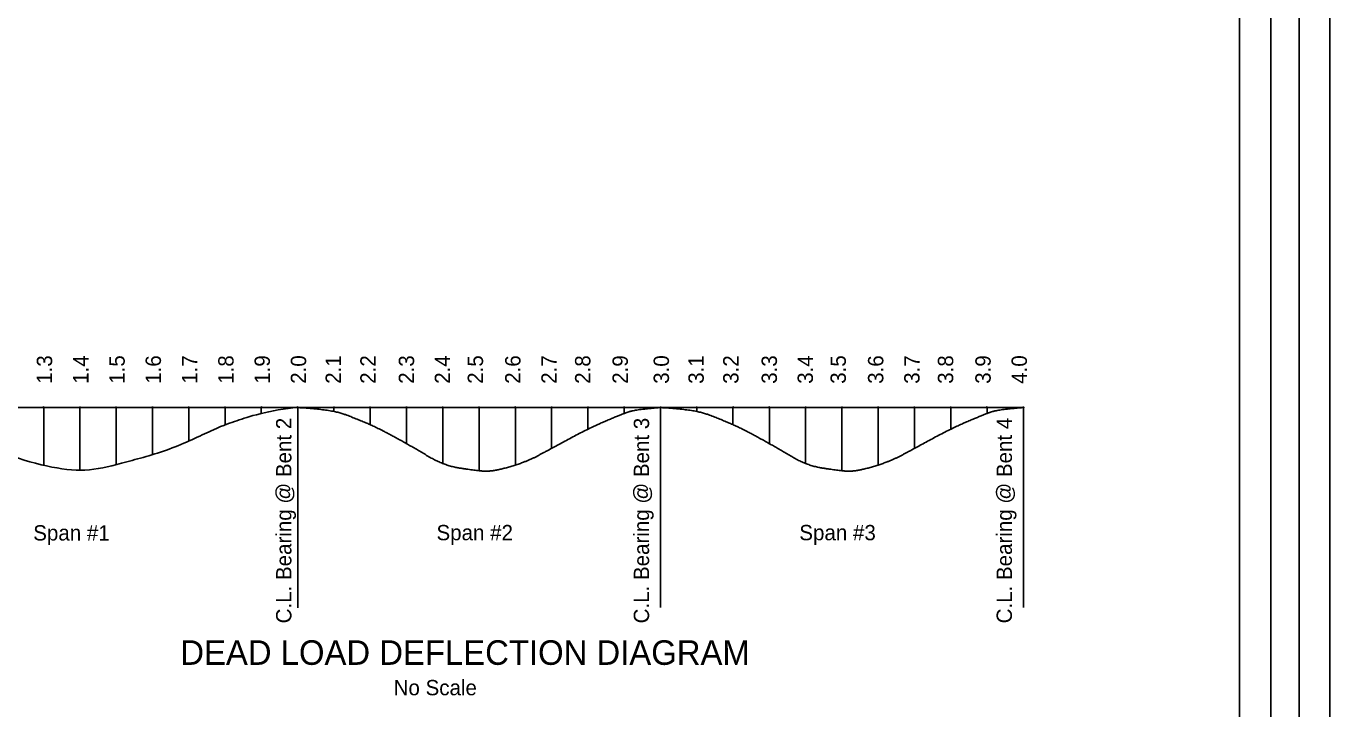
# Model space of a CAD drawing. Extents: x 208.5 to 250.5, y 328.7 to 350.7.
# Drawn here: x 232.41 to 243.03, y 334.16 to 339.73 of the extents above; entities that cross this region are included whole.
import ezdxf

# ---------------------------------------------------------------- set-up
doc = ezdxf.new("R2010")
doc.units = 0
for name, color, linetype in [('border', 7, 'Continuous'), ('Border 2660-Hwy18 - Level 62', 7, 'Continuous'), ('Border 2660-Hwy18 - Level 63', 7, 'Continuous'), ('Dimensions', 7, 'Continuous'), ('Level 20', 7, 'Continuous'), ('Level 25', 7, 'Continuous'), ('Level 40', 7, 'Continuous'), ('Level 41', 7, 'Continuous'), ('Level 62 PDF', 7, 'Continuous')]:
    doc.layers.add(name, color=color, linetype=linetype)

msp = doc.modelspace()

# ---------------------------------------------------------------- linework, layer by layer
at = {"layer": 'border'}
msp.add_line((242.291, 329.584), (242.291, 350.129), dxfattribs=at)
at = {"layer": 'Border 2660-Hwy18 - Level 62'}
msp.add_lwpolyline([(208.659, 350.715), (242.778, 350.715), (242.778, 328.905), (208.659, 328.905)], close=True, dxfattribs=at)
at = {"layer": 'Border 2660-Hwy18 - Level 63'}
msp.add_lwpolyline([(208.548, 350.572), (242.548, 350.572), (242.548, 329.202), (208.548, 329.202)], close=True, dxfattribs=at)
at = {"layer": 'Dimensions'}
for centre in [(232.556, 336.619), (232.851, 336.619), (233.146, 336.619), (233.442, 336.619), (233.737, 336.619), (234.033, 336.619), (234.328, 336.619), (234.624, 336.619), (234.919, 336.619), (235.214, 336.619), (235.51, 336.619), (235.805, 336.619), (236.101, 336.619), (236.396, 336.619), (236.691, 336.619), (236.987, 336.619), (237.282, 336.619), (237.578, 336.619), (237.873, 336.619), (238.168, 336.619), (238.464, 336.619), (238.759, 336.619), (239.055, 336.619), (239.35, 336.619), (239.645, 336.619), (239.941, 336.619), (240.236, 336.619), (240.532, 336.619)]:
    msp.add_circle(centre, 0.004, dxfattribs=at)
at = {"layer": 'Level 20'}
for p, q in [((234.624, 334.987), (234.624, 336.619)), ((237.578, 335.135), (237.578, 336.619)), ((237.578, 334.988), (237.578, 336.619)), ((240.532, 335.135), (240.532, 336.619)), ((240.532, 335.135), (240.532, 336.619)), ((240.532, 334.988), (240.532, 336.619))]:
    msp.add_line(p, q, dxfattribs=at)
at = {"layer": 'Level 25'}
for p, q in [((231.669, 336.619), (234.624, 336.619)), ((237.578, 336.619), (234.624, 336.619)), ((240.532, 336.619), (237.578, 336.619))]:
    msp.add_line(p, q, dxfattribs=at)
at = {"layer": 'Level 41'}
for p, q in [((232.556, 336.619), (232.556, 336.148)), ((232.851, 336.619), (232.851, 336.108)), ((233.146, 336.619), (233.146, 336.153)), ((233.442, 336.619), (233.442, 336.235)), ((233.737, 336.619), (233.737, 336.346)), ((234.033, 336.619), (234.033, 336.478)), ((234.328, 336.619), (234.328, 336.57)), ((234.919, 336.619), (234.919, 336.583)), ((235.214, 336.619), (235.214, 336.478)), ((235.51, 336.619), (235.51, 336.324)), ((235.805, 336.619), (235.805, 336.167)), ((236.101, 336.619), (236.101, 336.105)), ((236.396, 336.619), (236.396, 336.152)), ((236.691, 336.619), (236.691, 336.286)), ((236.987, 336.619), (236.987, 336.441)), ((237.282, 336.619), (237.282, 336.568)), ((237.873, 336.619), (237.873, 336.583)), ((238.168, 336.619), (238.168, 336.478)), ((238.464, 336.619), (238.464, 336.324)), ((238.759, 336.619), (238.759, 336.167)), ((239.055, 336.619), (239.055, 336.105)), ((239.35, 336.619), (239.35, 336.152)), ((239.645, 336.619), (239.645, 336.286)), ((239.941, 336.619), (239.941, 336.441)), ((240.236, 336.619), (240.236, 336.568))]:
    msp.add_line(p, q, dxfattribs=at)
for points, degree in [([(231.671, 336.619), (231.764, 336.538), (231.952, 336.398), (232.247, 336.228), (232.641, 336.12), (232.928, 336.094), (233.215, 336.172), (233.607, 336.276), (233.972, 336.459), (234.129, 336.511), (234.285, 336.564), (234.524, 336.615), (234.624, 336.618)], 3), ([(234.623, 336.618), (234.899, 336.603), (235.108, 336.525), (235.29, 336.446), (235.551, 336.303), (235.812, 336.146), (236.06, 336.107), (236.204, 336.094), (236.478, 336.172), (236.674, 336.276), (236.987, 336.446), (237.261, 336.564), (237.378, 336.603), (237.578, 336.619)], 2), ([(237.578, 336.618), (237.853, 336.603), (238.062, 336.525), (238.244, 336.446), (238.505, 336.303), (238.766, 336.146), (239.014, 336.107), (239.158, 336.094), (239.432, 336.172), (239.628, 336.276), (239.941, 336.446), (240.215, 336.564), (240.332, 336.603), (240.532, 336.619)], 2)]:
    msp.add_open_spline(points, degree=degree, dxfattribs=at)
at = {"layer": 'Level 62 PDF'}
msp.add_lwpolyline([(208.909, 350.548), (243.028, 350.548), (243.028, 328.739), (208.909, 328.739)], close=True, dxfattribs=at)

# ---------------------------------------------------------------- texts
at = {"layer": 'Level 40'}
for s, height, rotation, p in [('1.3', 0.125, 89.9998, (232.625, 336.812)), ('1.4', 0.125, 89.9998, (232.921, 336.812)), ('1.5', 0.125, 89.9998, (233.216, 336.812)), ('1.6', 0.125, 89.9998, (233.511, 336.812)), ('1.7', 0.125, 89.9998, (233.807, 336.812)), ('1.8', 0.125, 89.9998, (234.102, 336.812)), ('1.9', 0.125, 89.9998, (234.398, 336.812)), ('2.0', 0.125, 89.9998, (234.693, 336.812)), ('2.1', 0.125, 89.9998, (234.976, 336.812)), ('2.2', 0.125, 89.9998, (235.259, 336.812)), ('2.3', 0.125, 89.9998, (235.572, 336.812)), ('2.4', 0.125, 89.9998, (235.865, 336.812)), ('2.5', 0.125, 89.9998, (236.133, 336.812)), ('2.6', 0.125, 89.9998, (236.438, 336.812)), ('2.7', 0.125, 89.9998, (236.733, 336.812)), ('2.8', 0.125, 89.9998, (237.007, 336.812)), ('2.9', 0.125, 89.9998, (237.312, 336.812)), ('3.0', 0.125, 89.9998, (237.647, 336.812)), ('3.1', 0.125, 89.9998, (237.93, 336.812)), ('3.2', 0.125, 89.9998, (238.213, 336.812)), ('3.3', 0.125, 89.9998, (238.526, 336.812)), ('3.4', 0.125, 89.9998, (238.819, 336.812)), ('3.5', 0.125, 89.9998, (239.087, 336.812)), ('3.6', 0.125, 89.9998, (239.392, 336.812)), ('3.7', 0.125, 89.9998, (239.687, 336.812)), ('3.8', 0.125, 89.9998, (239.961, 336.812)), ('3.9', 0.125, 89.9998, (240.266, 336.812)), ('4.0', 0.125, 89.9998, (240.561, 336.812)), ('C.L. Bearing @ Bent 2', 0.12501, 89.9998, (234.573, 334.86)), ('C.L. Bearing @ Bent 3', 0.12501, 89.9998, (237.485, 334.86)), ('C.L. Bearing @ Bent 4', 0.12501, 89.9998, (240.439, 334.86)), ('Span #1 ', 0.125, 359.9998, (232.471, 335.535)), ('Span #2', 0.125, 359.9998, (235.754, 335.537)), ('Span #3', 0.125, 359.9998, (238.708, 335.537))]:
    msp.add_text(s, height=height, rotation=rotation, dxfattribs=at).set_placement(p)
msp.add_text('No Scale', height=0.125, dxfattribs=at).set_placement((235.405, 334.274))
at = {"layer": 'Level 41'}
msp.add_text(' DEAD LOAD DEFLECTION DIAGRAM ', height=0.2, dxfattribs=at).set_placement((233.594, 334.522))

doc.saveas('drawing.dxf')
